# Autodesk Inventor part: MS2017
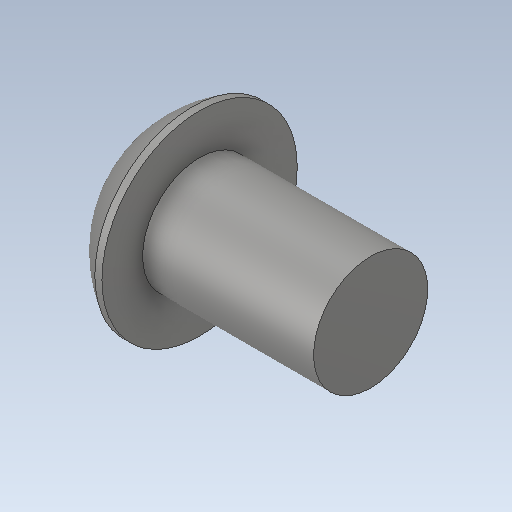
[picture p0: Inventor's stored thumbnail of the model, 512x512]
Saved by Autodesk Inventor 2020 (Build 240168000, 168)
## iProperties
Created: 2015-11
Part Number: MS2017
Material: Ogólny
Document SubType Name: Modeling
Designer: Tomasz
Density: 1 g/cm^3
Appearance: Domyślna
Sending System: SolidWorks 2017
Last Author: Tomasz
Last Saved: 2017-09-17
Author: Tomasz
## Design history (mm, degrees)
feature "Imported1"
node "Bryła1"
